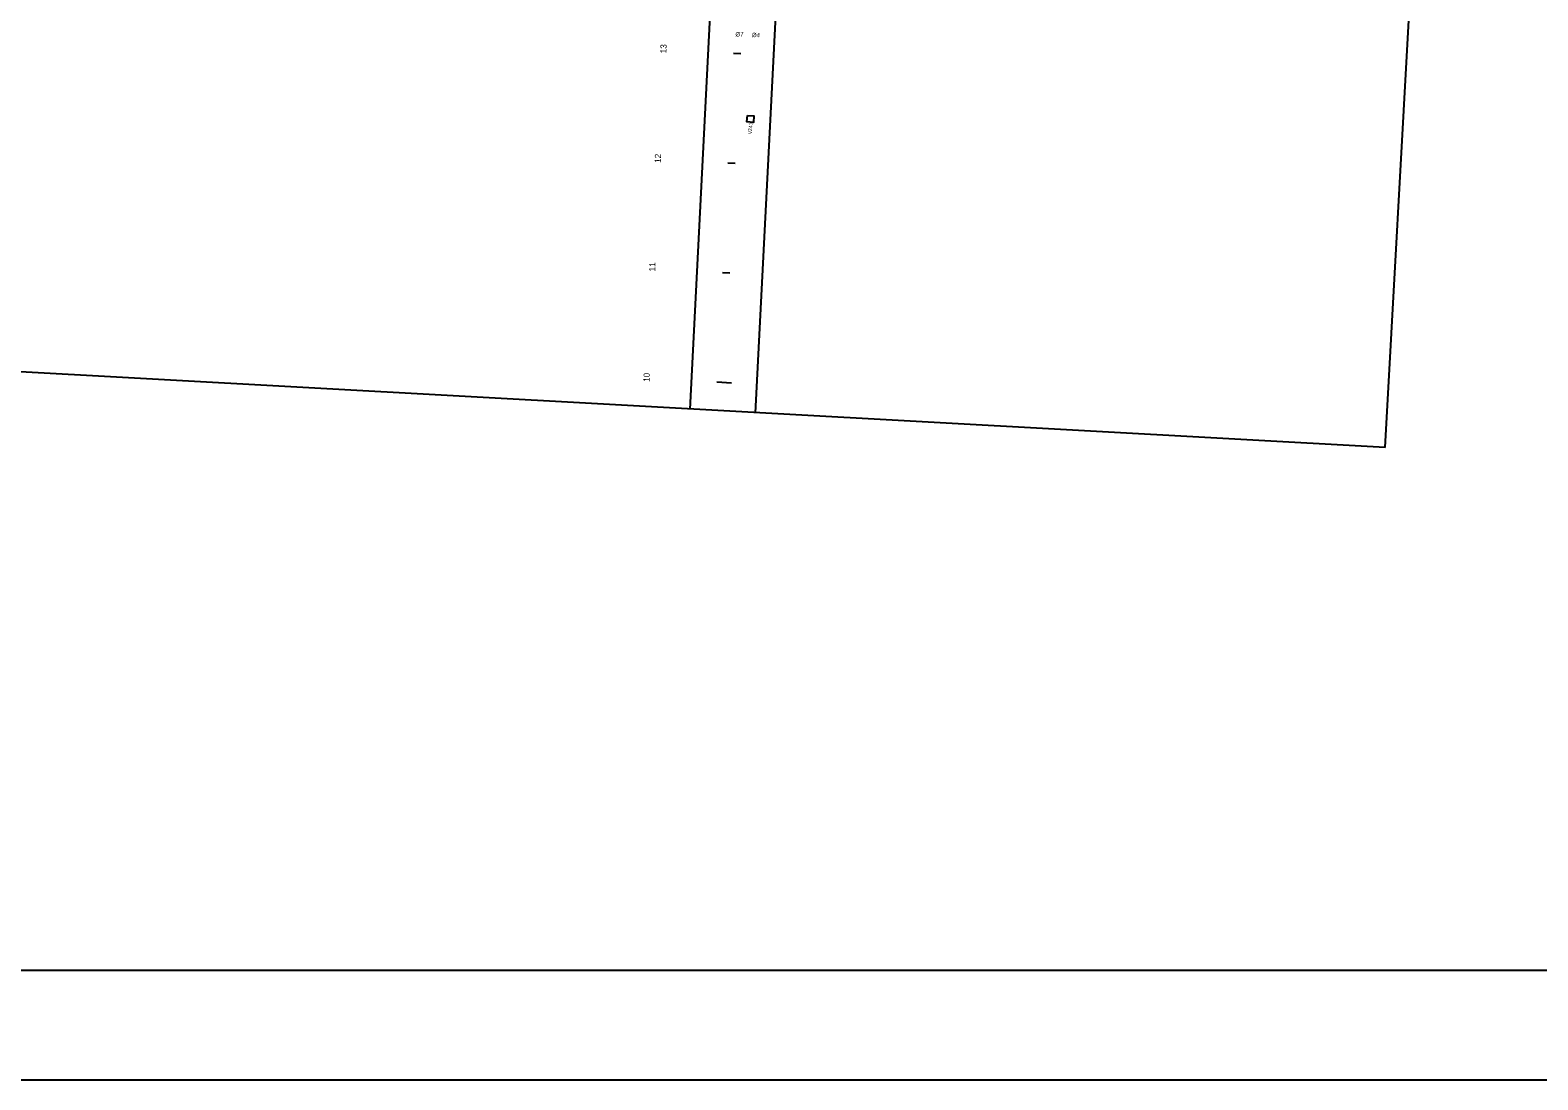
# Model space of a CAD drawing. Extents: x 0 to 1361828, y 0 to 1470398.
# Drawn here: x 682944 to 684319, y 733868 to 734825 of the extents above; entities that cross this region are included whole.
import ezdxf

# ---------------------------------------------------------------- set-up
doc = ezdxf.new("R2010")
doc.units = 0
for name, color, linetype in [('$', 7, 'Continuous'), ('border All Plan 20-40_Border 3 - Level 1', 7, 'Continuous'), ('C-TOPO', 7, 'Continuous'), ('C-TOPO-FEAT', 7, 'Continuous'), ('R_Horz Alg Station', 7, 'Continuous'), ('RW-EX', 7, 'Continuous'), ('TITEXT', 7, 'Continuous'), ('V-NODE', 7, 'Continuous'), ('Video-Zones-pr', 7, 'Continuous')]:
    doc.layers.add(name, color=color, linetype=linetype)

msp = doc.modelspace()

# ---------------------------------------------------------------- linework, layer by layer
at = {"layer": '$'}
msp.add_lwpolyline([(679553.9, 733968.3), (687571.1, 733968.3), (687571.1, 736006.7), (679553.9, 736006.7), (679553.9, 733968.3)], dxfattribs=at)
at = {"layer": 'border All Plan 20-40_Border 3 - Level 1'}
for q in [(684236.6, 735470.4), (682601.3, 734532.1)]:
    msp.add_line((684179.8, 734444.7), q, dxfattribs=at)
at = {"layer": 'C-TOPO'}
msp.add_lwpolyline([(679453.9, 733868.3), (687671.1, 733868.3), (687671.1, 736106.7), (679453.9, 736106.7), (679453.9, 733868.3)], dxfattribs=at)
at = {"layer": 'C-TOPO-FEAT'}
msp.add_lwpolyline([(679553.9, 733968.3), (687571.1, 733968.3), (687571.1, 736006.7), (679553.9, 736006.7), (679553.9, 733968.3)], dxfattribs=at)
at = {"layer": 'R_Horz Alg Station'}
for points in [[(683585.8, 734804.1), (683592.4, 734803.8)], [(683580.6, 734704.2), (683587.3, 734703.9)], [(683575.5, 734604.4), (683582.2, 734604)], [(683570.4, 734504.5), (683583.7, 734503.8)]]:
    msp.add_lwpolyline(points, dxfattribs=at)
at = {"layer": 'RW-EX'}
for p, q in [((683569.7, 734945.9), (683545.8, 734479.8)), ((683605.7, 734476.5), (683629.2, 734934.7))]:
    msp.add_line(p, q, dxfattribs=at)
at = {"layer": 'V-NODE'}
msp.add_lwpolyline([(679553.9, 733968.3), (687571.1, 733968.3), (687571.1, 736006.7), (679553.9, 736006.7), (679553.9, 733968.3)], dxfattribs=at)
at = {"layer": 'Video-Zones-pr'}
msp.add_lwpolyline([(683598.3, 734747.5), (683604.3, 734747.1), (683603.9, 734741.1), (683597.9, 734741.6), (683598.3, 734747.5)], dxfattribs=at)

# ---------------------------------------------------------------- texts
at = {"layer": '$'}
for s, height, rotation, p in [('13', 5.6, 88.3887, (683524.5, 734804)), ('VZ41', 3.2, 87.0608, (683602.3, 734730.3)), ('12', 5.6, 88.3887, (683519.4, 734704.1)), ('11', 5.6, 88.3887, (683514.3, 734605.2)), ('10', 5.6, 88.3887, (683509.1, 734504.4))]:
    msp.add_text(s, height=height, rotation=rotation, dxfattribs=at).set_placement(p)
at = {"layer": 'TITEXT'}
for s, p in [('%%C7', (683587.3, 734819.6)), ('%%C4', (683602.3, 734819))]:
    msp.add_text(s, height=4, rotation=356.2723, dxfattribs=at).set_placement(p)

doc.saveas('drawing.dxf')
